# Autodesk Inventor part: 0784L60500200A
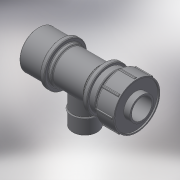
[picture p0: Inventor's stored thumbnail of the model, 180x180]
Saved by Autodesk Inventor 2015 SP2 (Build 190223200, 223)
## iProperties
Created: 2018-02
Part Number: 0784L60500200A
Material: Generic
Description: PLASSON MODULAR MALE TEE 50-2"-50
Document SubType Name: Modeling
Designer: KIM
Density: 1 g/cm^3
Appearance: Default
Author: KIM
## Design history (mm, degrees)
derived "0784L6.ipt"
feature "Solid1::0784L6.ipt"
feature "Solid2::0784L6.ipt"
tag "TaggingFeature1"
body "Solid1"
other parameters: "d26" = 38.55665, "d51" = 2, "d52" = 4.8, "d54" = 0, "d55" = 2, "d56" = 1, "d58" = 360 deg, "d60" = 1, "d63" = 1, "d65" = 0, "d67" = 0, "d69" = 183, "d70" = 82, "d71" = 59.614, "d73" = 93.12, "d74" = 75, "d75" = 35, "d76" = 88.32, "d77" = 41, "d79" = 46.5, "d80" = 42.5, "d82" = 7, "d83" = 86.4, "d84" = 86.4, "d86" = 72, "d88" = 76.8, "d89" = 67.2, "d90" = 10.25, "d91" = 38.95, "d92" = 81.6, "d93" = 45.1, "d94" = 36.9, "d95" = 8.2, "d96" = 55.35, "d97" = 54.9, "d98" = 67.2, "d99" = 48, "d100" = 43.2, "d101" = 26, "d102" = 44.7105, "d103" = 65.5754, "d104" = 28.6, "E_" = 96, "H_" = 183, "l_1" = 41, "l_2" = 26, "A_" = 82, "d_" = 1, "R_" = 59.614, "ODP_" = 75, "LPT_" = 35
